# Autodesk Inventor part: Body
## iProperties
Shininess: 77.0
Length Units: 11269
Angle Units: 11279
Time Units: 11290
Mass Units: 11283
Length Display Precision: 3
Angle Display Precision: 2
Created: 2002-01
Part Number: Body
Document SubType Name: Modeling
Designer: ***
Density: 0.0
Volumn: 0.0
Area: 0.0
PropertySet Name: Model Information
Control State: 0
Master: False
Checked Out: False
Author: ***
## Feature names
1. Extrusion1
2. Extrusion2
3. Circular Pattern1
4. Mirror1
5. Extrusion3
6. Extrusion4
7. Hole1
8. Hole2
9. Circular Pattern2
